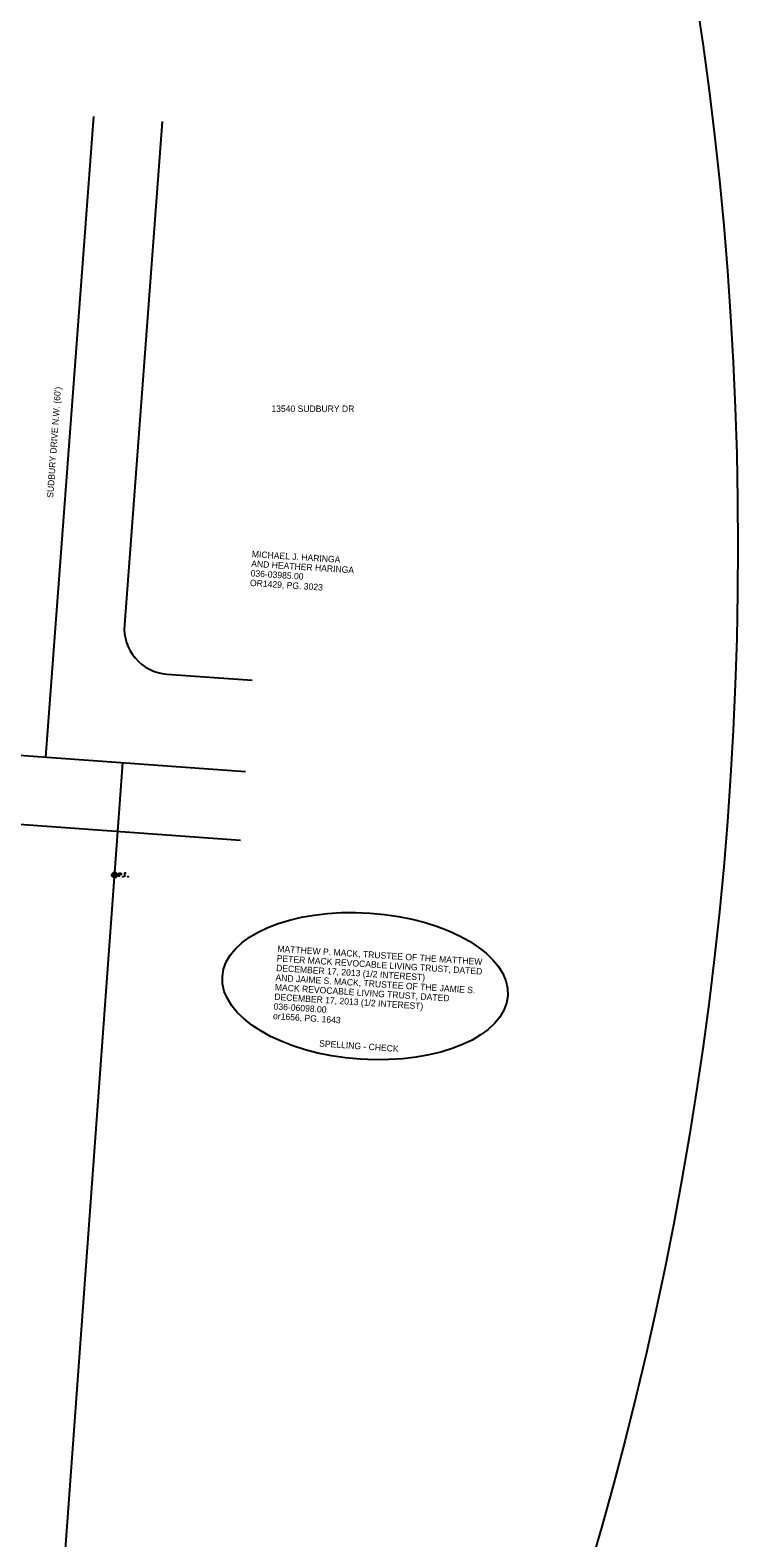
# Model space of a CAD drawing. Extents: x 1898254 to 1901377, y 701554 to 704886.
# Drawn here: x 1901068 to 1901377, y 702797 to 703455 of the extents above; entities that cross this region are included whole.
import ezdxf

# ---------------------------------------------------------------- set-up
doc = ezdxf.new("R2010")
doc.units = 0
for name, color, linetype in [('DV_X_Property_Line', 7, 'Continuous'), ('DV_X_Text', 7, 'Continuous'), ('RW_X_CL', 7, 'Continuous'), ('RW_X_Esmt_SH', 7, 'Continuous'), ('RW_X_Fee_RW', 7, 'Continuous'), ('RW_X_Text', 7, 'Continuous'), ('SC_Scratch2', 7, 'Continuous'), ('SC_Scratch9', 7, 'Continuous'), ('SV_X_Mon_Cells_Found', 7, 'Continuous')]:
    doc.layers.add(name, color=color, linetype=linetype)

msp = doc.modelspace()

# ---------------------------------------------------------------- linework, layer by layer
at = {"layer": 'DV_X_Property_Line'}
msp.add_line((1901070.53, 702612.79), (1901108.73, 703135.32), dxfattribs=at)
at = {"layer": 'RW_X_CL'}
for p, q in [((1901095.87, 703417.31), (1901075, 703137.79)), ((1899815.76, 703229.84), (1901162.17, 703131.42))]:
    msp.add_line(p, q, dxfattribs=at)
at = {"layer": 'RW_X_Esmt_SH'}
msp.add_line((1900608.03, 703141.85), (1901159.98, 703101.5), dxfattribs=at)
at = {"layer": 'RW_X_Fee_RW'}
for p, q in [((1901125.79, 703415.08), (1901109.39, 703195.47)), ((1901127.88, 703174.03), (1901165.09, 703171.31))]:
    msp.add_line(p, q, dxfattribs=at)
msp.add_arc((1901129.33, 703193.98), 20, 175.7289, 265.81918, dxfattribs=at)
at = {"layer": 'SC_Scratch2'}
msp.add_circle((1899815.76, 703229.84), 1561.35, dxfattribs=at)
at = {"layer": 'SC_Scratch9'}
msp.add_ellipse((1901214.42, 703037.84), major_axis=(62.26, -4.2), ratio=0.512235, dxfattribs=at)
at = {"layer": 'SV_X_Mon_Cells_Found'}
for points in [[(1901107.14, 703085.52), (1901107.14, 703087.12), (1901107.67, 703087.12), (1901107.73, 703087.11), (1901107.81, 703087.08), (1901107.84, 703087.06), (1901107.87, 703087.03), (1901107.92, 703086.97), (1901107.95, 703086.9), (1901107.97, 703086.8), (1901107.97, 703086.65), (1901107.96, 703086.6), (1901107.94, 703086.53), (1901107.89, 703086.44), (1901107.85, 703086.4), (1901107.82, 703086.38), (1901107.76, 703086.35), (1901107.67, 703086.34), (1901107.14, 703086.34)], [(1901108.79, 703085.73), (1901108.84, 703085.73), (1901108.87, 703085.71), (1901108.91, 703085.66), (1901108.91, 703085.59), (1901108.87, 703085.54), (1901108.84, 703085.52), (1901108.79, 703085.52), (1901108.75, 703085.54), (1901108.72, 703085.59), (1901108.72, 703085.66), (1901108.75, 703085.71), (1901108.79, 703085.73)], [(1901110.15, 703087.12), (1901109.39, 703087.12), (1901109.39, 703085.52)], [(1901109.39, 703086.34), (1901109.93, 703086.34)], [(1901110.94, 703085.73), (1901110.99, 703085.73), (1901111.02, 703085.71), (1901111.06, 703085.66), (1901111.06, 703085.59), (1901111.02, 703085.54), (1901110.99, 703085.52), (1901110.94, 703085.52), (1901110.9, 703085.54), (1901110.87, 703085.59), (1901110.87, 703085.66), (1901110.9, 703085.71), (1901110.94, 703085.73)]]:
    msp.add_lwpolyline(points, dxfattribs=at)
for radius in [1.2, 0.495]:
    msp.add_circle((1901105.15, 703086.32), radius, dxfattribs=at)

# ---------------------------------------------------------------- texts
at = {"layer": 'DV_X_Text'}
msp.add_text('13540 SUDBURY DR', height=2.8, dxfattribs=at).set_placement((1901173.52, 703288.42))
for s, p in [('MICHAEL J. HARINGA', (1901164.94, 703225.03)), ('AND HEATHER HARINGA ', (1901164.67, 703220.84)), ('OR1429, PG. 3023', (1901164.13, 703212.46)), ('036-03985.00', (1901164.4, 703216.65)), ('PETER MACK REVOCABLE LIVING TRUST, DATED ', (1901175.8, 703048.59)), ('MATTHEW P. MACK, TRUSTEE OF THE MATTHEW ', (1901176.06, 703052.78)), ('DECEMBER 17, 2013 (1/2 INTEREST)', (1901175.53, 703044.4)), ('AND JAIME S. MACK, TRUSTEE OF THE JAMIE S. ', (1901175.26, 703040.2)), ('MACK REVOCABLE LIVING TRUST, DATED ', (1901174.99, 703036.01)), ('036-06098.00', (1901174.45, 703027.63)), ('DECEMBER 17, 2013 (1/2 INTEREST)', (1901174.72, 703031.82)), ('or1656, PG. 1643', (1901174.18, 703023.44))]:
    msp.add_text(s, height=2.8, rotation=356.3351, dxfattribs=at).set_placement(p)
at = {"layer": 'RW_X_Text'}
msp.add_text("SUDBURY DRIVE N.W. (60')", height=2.8, rotation=85.93252, dxfattribs=at).set_placement((1901078.31, 703250.84))
at = {"layer": 'SC_Scratch9'}
msp.add_text('SPELLING - CHECK', height=2.8, rotation=355.93252, dxfattribs=at).set_placement((1901194.3, 703011.51))

doc.saveas('drawing.dxf')
